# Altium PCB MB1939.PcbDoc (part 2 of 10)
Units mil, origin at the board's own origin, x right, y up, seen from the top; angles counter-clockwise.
Board outline 5910.64 x 4335.93 mil, 6 copper layers (Top Layer, l2_GND, L3_SIG, L4_VCC, L5_GND, Bottom Layer), stack 58.424 mil thick; 635 components, 489 nets, 2289 pads, 1388 vias.
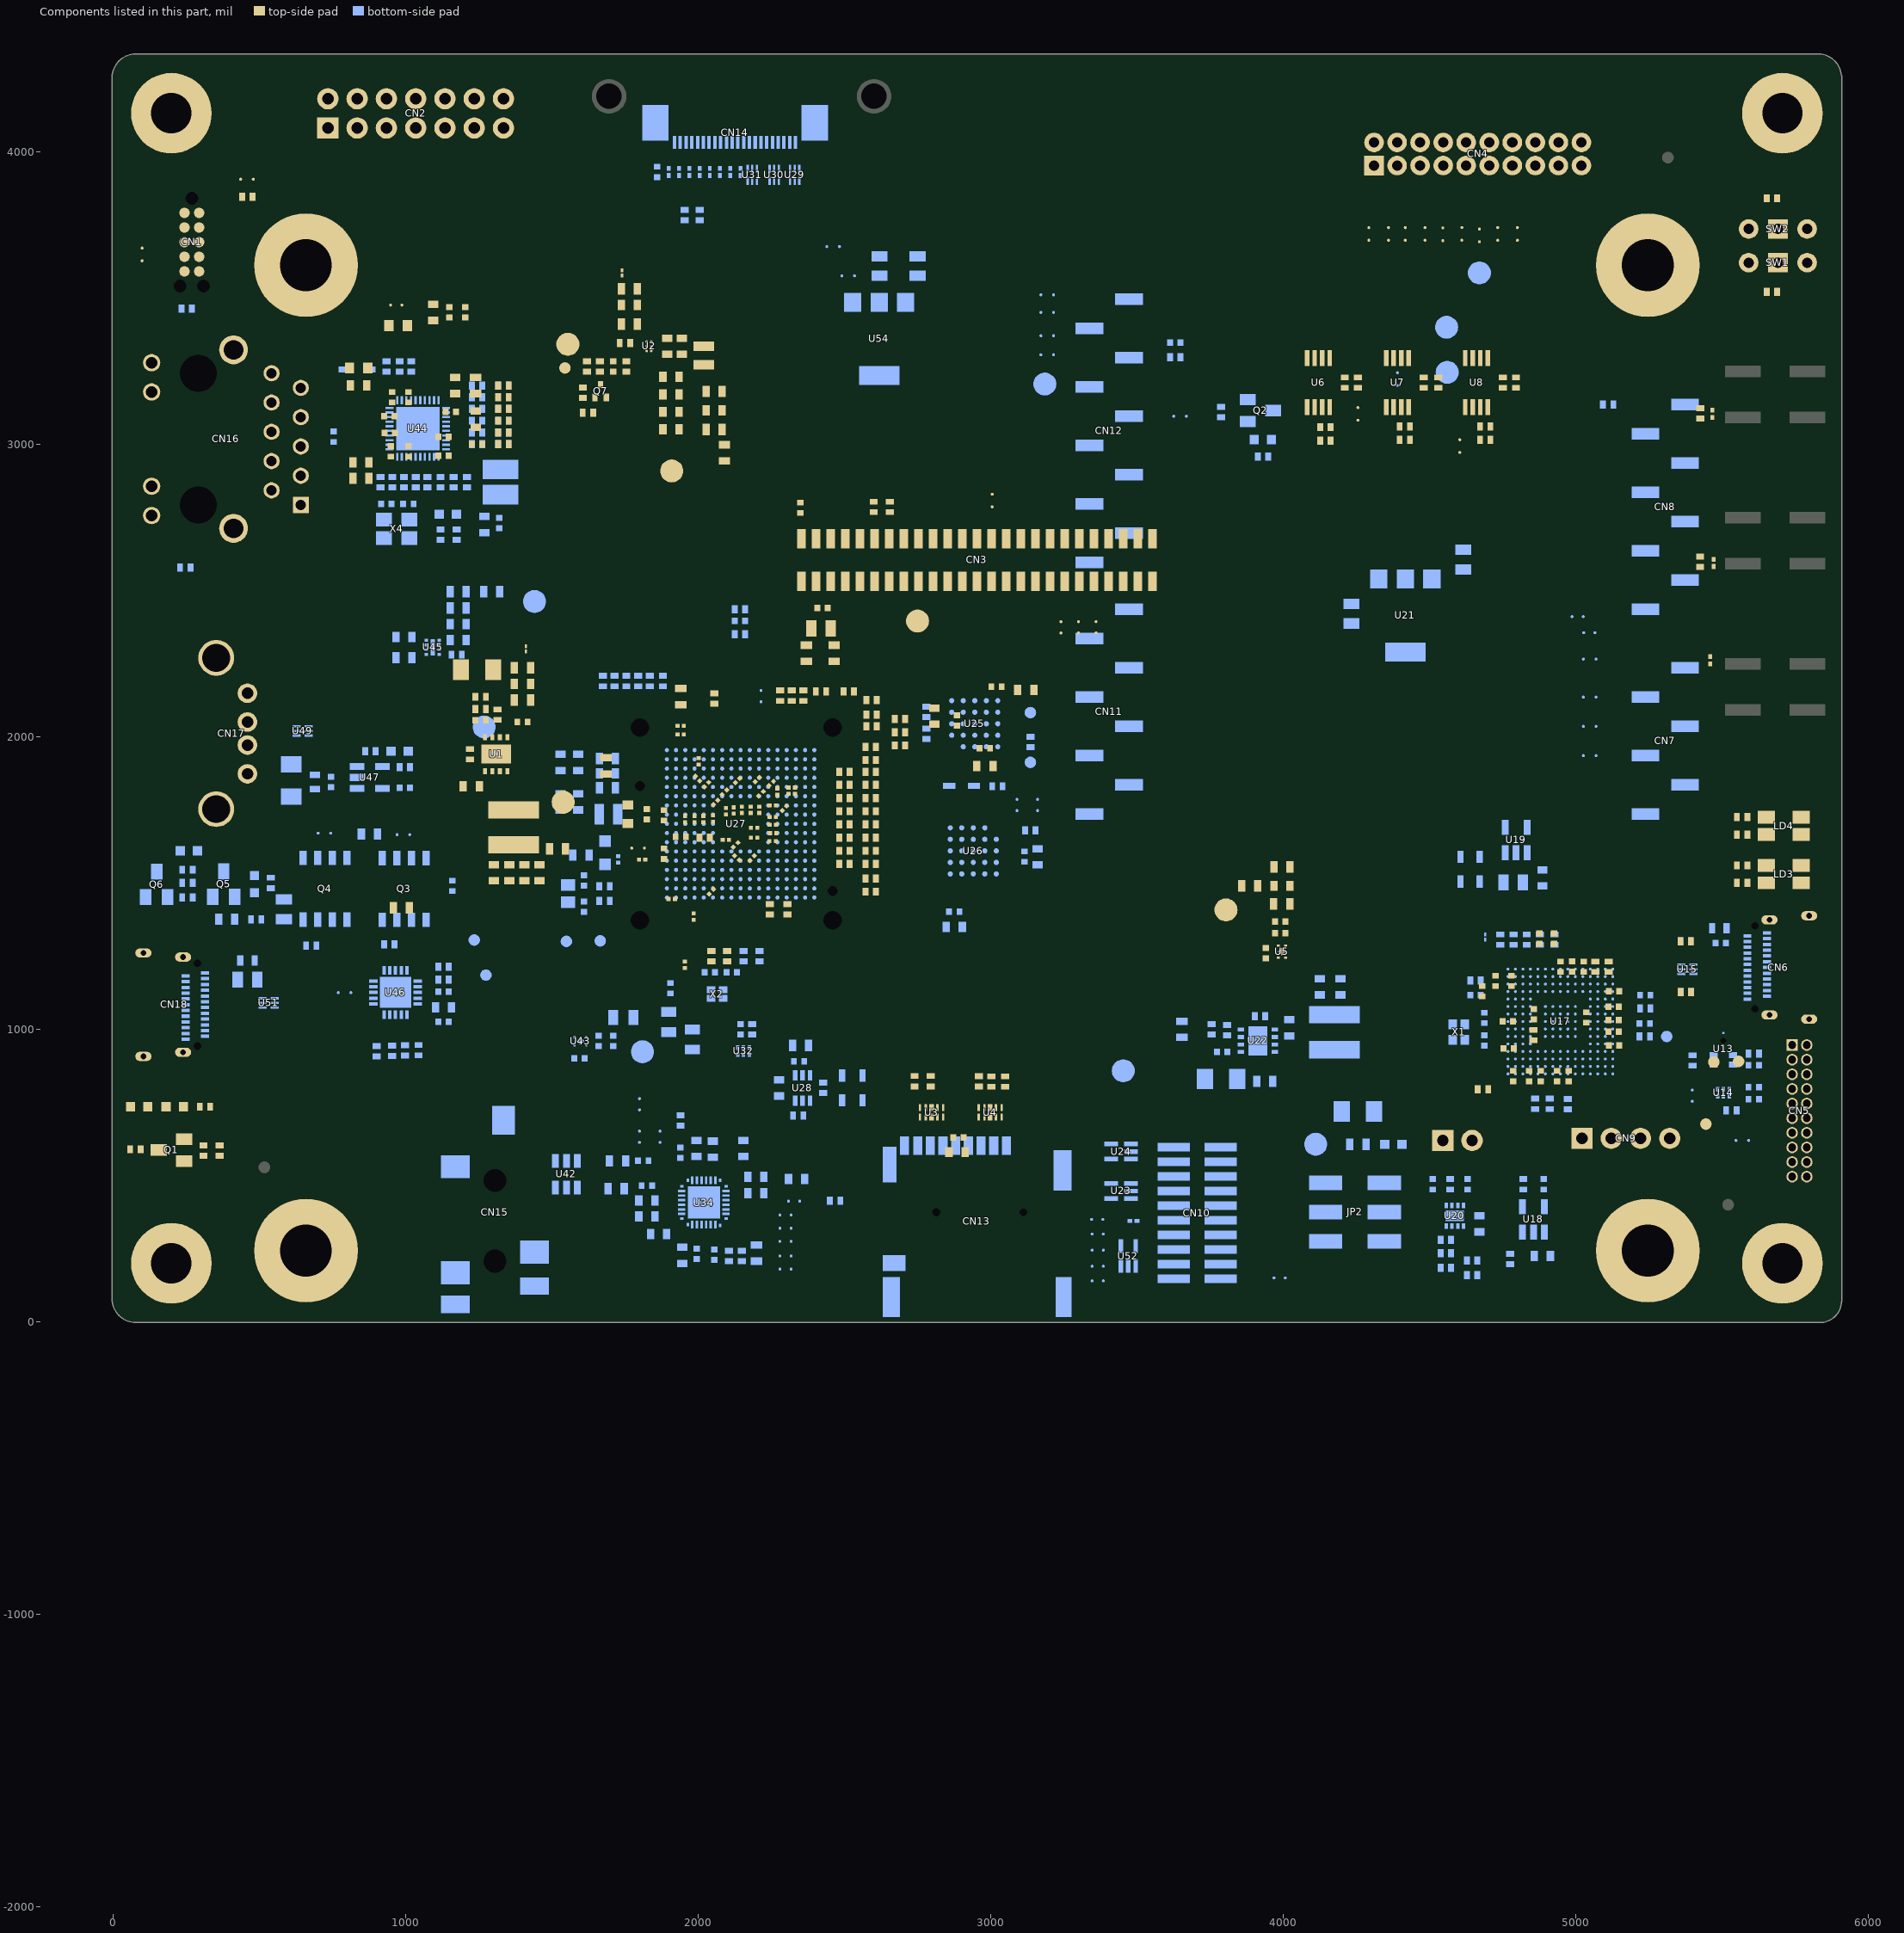
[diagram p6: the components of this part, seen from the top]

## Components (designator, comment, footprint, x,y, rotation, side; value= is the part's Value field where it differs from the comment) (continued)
R151 "Resistor" R0402 2142.73,2350 r180 bottom locked value=10K
R152 "Resistor" R0402 2142.73,2435 r0 bottom locked value=140K
R153 "Resistor" R0402 2155,1250 r90 bottom locked value=1K5
R154 "Resistor" R0402 2100,1250 r90 bottom locked value=0R
R155 "Resistor" R0402 2045,1250 r90 bottom locked value=0R
R156 "Resistor" R0402 1940,687.72 r270 bottom value=2K2
R157 "Resistor" R0402 1620,3265 r90 top value=422K
R158 "Resistor" R0402 1606.3,3175.2 r90 top value=150K
R159 "Resistor" R0805 1981.1,965 r90 bottom value=0R
R160 "Resistor" R0402 1880,2190 r90 bottom locked value=22R
R161 "Resistor" R0402 1835,2190 r90 bottom locked value=22R
R162 "Resistor" R0402 1795,2190 r90 bottom locked value=22R
R163 "Resistor" R0805 1745.01,1040 r0 bottom locked value=0R
R164 "Resistor" R0603 1725,550 r0 bottom value=20R
R165 "Resistor" R0603 1720,455 r0 bottom value=20R
R166 "Resistor" R0402 1755,2190 r90 bottom locked value=22R
R167 "Resistor" R0603 1690.01,1825 r180 bottom locked value=0R
R168 "Resistor" R0603 1690.01,1925 r180 bottom locked value=50mR
R169 "Resistor" R0402 1715,2190 r90 bottom locked value=22R
R170 "Resistor" R0402 1680.4,1438.69 r0 bottom locked value=0R
R171 "Resistor" R0402 1680.4,1488.69 r0 bottom locked value=0R
R172 "Resistor" R0402 1675,2190 r90 bottom locked value=22R
R173 "Resistor" R0603 1600.01,1595 r180 bottom locked value=0R
R174 "Resistor" R0402 1335.01,3080 r0 bottom locked value=4K7
R175 "Resistor" R0402 1335.01,3200 r0 bottom locked value=4K7
R176 "Resistor" R0402 1335,3000 r0 bottom locked value=4K7
R177 "Resistor" R0402 1335,3040 r0 bottom locked value=4K7
R178 "Resistor" R0402 1335,3120 r0 bottom locked value=4K7
R179 "Resistor" R0603 1295.01,2495 r0 bottom locked value=0R
R180 "Resistor" R0402 1245.01,3000 r180 bottom locked value=22R
R181 "Resistor" R0402 1245.01,3040 r180 bottom locked value=22R
R182 "Resistor" R0402 1245.01,3080 r180 bottom locked value=22R
R183 "Resistor" R0402 1245.01,3120 r180 bottom locked value=22R
R184 "Resistor" R0402 1245.01,3160 r180 bottom locked value=22R
R185 "Resistor" R0402 1245.01,3200 r180 bottom locked value=22R
R186 "Resistor" R0402 1210,2870 r270 bottom locked value=1K5
R187 "Resistor" R0603 1180.01,2440 r0 bottom locked value=0R
R188 "Resistor" R0603 1180.01,2495 r0 bottom locked value=330mR
R189 "Resistor" R0402 1175,2280 r180 bottom locked value=0R
R190 "Resistor" R0402 1175,2690 r90 bottom locked value=510R
R191 "Resistor" R0402 1165,2870 r90 bottom locked value=4K7
R192 "Resistor" R0402 1130.01,1169 r0 bottom value=24K
R193 "Resistor" R0402 1130.01,1214 r180 bottom value=100K
R194 "Resistor" R0402 1120,2690 r90 bottom locked value=4K7
R195 "Resistor" R0402 1120,2870 r90 bottom locked value=4K7
R196 "Resistor" R0402 1075,2870 r90 bottom locked value=22R
R197 "Resistor" R0402 1045.01,928.49 r270 bottom locked value=10K
R198 "Resistor" R0402 1035,2870 r90 bottom locked value=0R
R199 "Resistor" R0603 995.01,2270 r0 bottom locked value=0R
R200 "Resistor" R0402 1020,3265 r90 bottom locked value=1K5
R201 "Resistor" R0402 998,1895.51 r180 bottom locked value=100K
R202 "Resistor" R0402 999.01,927.49 r90 bottom locked value=0R
R203 "Resistor" R0402 995,2870 r270 bottom locked value=22R
R204 "Resistor" R0402 980,3265 r90 bottom locked value=1K5
R205 "Resistor" R0402 955,2870 r90 bottom locked value=0R
R206 "Resistor" R0402 954.01,926.49 r90 bottom locked value=0R
R207 "Resistor" R0402 935,3265 r270 bottom locked value=10K
R208 "Resistor" R0402 915,2870 r270 bottom locked value=2K49
R209 "Resistor" R0603 877,1667 r180 bottom value=0R
R210 "Resistor" R0402 902.01,924.49 r90 bottom locked value=100K
R211 "Resistor" R0402 880,1950 r0 bottom locked value=680R
R212 "Resistor" R0402 540,1500 r270 bottom locked value=270R
R213 "Resistor" R0402 490.01,1375 r180 bottom locked value=47K
R214 "Resistor" R0603 389.01,1375.94 r180 bottom locked value=22K
R215 "Resistor" R0402 255.01,1450 r180 bottom locked value=100K
R216 "Resistor" R0402 255.01,1500 r0 bottom locked value=47K
R217 "Resistor" R0402 255.01,1545 r0 bottom locked value=330R
R218 "Resistor" R0402 252.64,3462.83 r180 bottom locked value=510R
R219 "Resistor" R0402 247.64,2577.83 r0 bottom locked value=510R
R220 "Resistor" R0402 2022.28,1655 r0 top value=2R
R221 "Resistor" R0402 2005,3782.28 r90 bottom value=10K
R222 "Resistor" R0402 1954.02,3782.28 r90 bottom value=10K
R223 "Resistor" R0402 1623.6,3107.4 r180 top value=1M
R224 "Resistor" R0402 5425,3105 r270 top value=10K
R225 "Resistor" R0402 5424.29,2597.72 r270 top value=10K
R226 "Resistor" R0402 2150,225 r270 bottom value=0R
R227 "Resistor" R0402 2105,225 r270 bottom value=0R
R228 "Resistor" R0402 945,1290 r0 bottom value=1M3
R229 "Resistor" R0402 678,1286 r0 bottom value=1M3
SB1 "SB_ON" SOLDER-BRIDGE_R0603-0R 100,3650 r270 top locked value=0R
SB2 "SB_ON" SOLDER-BRIDGE_R0603-0R 456.4,3905 r0 top locked value=0R
SB3 "SB_ON" SOLDER-BRIDGE_R0402-0R 970.02,3475 r180 top locked value=0R
SB4 "SB_ON" SOLDER-BRIDGE_R0603-0R 1793,1619 r0 top value=0R
SB5 "SB_ON" SOLDER-BRIDGE_R0603-0R 3005,2805 r90 top locked value=0R
SB6 "SB_ON" SOLDER-BRIDGE_R0402-0R 3240,2375 r270 top locked value=0R
SB7 "SB_ON" SOLDER-BRIDGE_R0402-0R 3300,2375.32 r270 top locked value=0R
SB8 "SB_ON" SOLDER-BRIDGE_R0402-0R 3360,2375.32 r270 top locked value=0R
SB9 "SB_ON" SOLDER-BRIDGE_R0603-0R 4255,3105 r270 top locked value=0R
SB10 "SB_ON" SOLDER-BRIDGE_R0603-0R 4292.17,3716.06 r90 top locked value=0R
SB11 "SB_ON" SOLDER-BRIDGE_R0603-0R 4359.49,3716.06 r90 top locked value=0R
SB12 "SB_ON" SOLDER-BRIDGE_R0603-0R 4416.81,3716.06 r90 top locked value=0R
SB13 "SB_ON" SOLDER-BRIDGE_R0603-0R 4484.13,3716.06 r90 top locked value=0R
SB14 "SB_ON" SOLDER-BRIDGE_R0603-0R 4545,3715 r90 top locked value=0R
SB15 "SB_ON" SOLDER-BRIDGE_R0603-0R 4610,3716.38 r90 top locked value=0R
SB16 "SB_ON" SOLDER-BRIDGE_R0603-0R 4670,3715 r270 top locked value=0R
SB17 "SB_ON" SOLDER-BRIDGE_R0603-0R 4732.52,3716.06 r90 top locked value=0R
SB18 "SB_ON" SOLDER-BRIDGE_R0603-0R 4799.84,3716.06 r90 top locked value=0R
SB19 "SB_ON" SOLDER-BRIDGE_R0402-0R 5397.38,771.51 r90 bottom locked value=0R
SB20 "SB_ON" SOLDER-BRIDGE_R0603-0R 5045.02,1935 r0 bottom locked value=0R
SB21 "SB_ON" SOLDER-BRIDGE_R0603-0R 5045.02,2035 r0 bottom locked value=0R
SB22 "SB_ON" SOLDER-BRIDGE_R0603-0R 5045.02,2135 r0 bottom locked value=0R
SB23 "SB_ON" SOLDER-BRIDGE_R0603-0R 5045.02,2265 r0 bottom locked value=0R
SB25 "SB_ON" SOLDER-BRIDGE_R0603-0R 3645.02,3095 r0 bottom locked value=0R
SB26 "SB_ON" SOLDER-BRIDGE_R0402-0R 3367.28,245 r180 bottom value=0R
SB27 "SB_ON" SOLDER-BRIDGE_R0402-0R 3367.28,140 r180 bottom value=0R
SB28 "SB_ON" SOLDER-BRIDGE_R0402-0R 3367.28,190 r180 bottom value=0R
SB29 "SB_ON" SOLDER-BRIDGE_R0402-0R 3365.67,350 r180 bottom value=0R
SB30 "SB_ON" SOLDER-BRIDGE_R0402-0R 3367.28,300 r180 bottom value=0R
SB31 "SB_ON" SOLDER-BRIDGE_R0603-0R 3195,3305 r180 bottom locked value=0R
SB32 "SB_ON" SOLDER-BRIDGE_R0603-0R 3195,3370 r180 bottom locked value=0R
SB33 "SB_ON" SOLDER-BRIDGE_R0603-0R 3195,3450 r180 bottom locked value=0R
SB34 "SB_ON" SOLDER-BRIDGE_R0603-0R 3195,3510 r180 bottom locked value=0R
SB35 "SB_ON" SOLDER-BRIDGE_R0402-0R 3160,1765 r90 bottom locked value=0R
SB36 "SB_ON" SOLDER-BRIDGE_R0402-0R 3090,1765 r90 bottom locked value=0R
SB37 "SB_ON" SOLDER-BRIDGE_R0402-0R 2329.74,412.65 r180 bottom locked value=0R
SB38 "SB_ON" SOLDER-BRIDGE_R0402-0R 1800,745 r270 bottom value=0R
SB39 "SB_ON" SOLDER-BRIDGE_R0402-0R 1800,633.94 r270 bottom value=0R
SB40 "SB_ON" SOLDER-BRIDGE_R0402-0R 1870,633.94 r270 bottom value=0R
SB41 "SB_ON" SOLDER-BRIDGE_R0603-0R 5570.32,620 r180 bottom value=0R
SB42 "SB_ON" SOLDER-BRIDGE_R0402-0R 5007.28,2410 r180 bottom value=0R
SB43 "SB_ON" SOLDER-BRIDGE_R0402-0R 2215,2140 r270 bottom locked value=0R
SB44 "SB_ON" SOLDER-BRIDGE_R0402-0R 5044.33,2355 r0 bottom value=0R
SB45 "SB_ON" SOLDER-BRIDGE_R0603-0R 2459.59,3674.9 r0 bottom value=0R
SB46 "SB_ON" SOLDER-BRIDGE_R0603-0R 995,1665 r180 bottom locked value=0R
SB47 "SB_ON" SOLDER-BRIDGE_R0603-0R 790.02,1125 r0 bottom locked value=0R
SB48 "SB_ON" SOLDER-BRIDGE_R0603-0R 725,1670 r180 bottom value=0R
SB49 "SB_ON" SOLDER-BRIDGE_R0603-0R 4603,2995 r270 top value=0R
SB51 "SB_ON" SOLDER-BRIDGE_R0603-0R 4390,3220 r90 bottom value=0R
SB53 "SB_ON" SOLDER-BRIDGE_R0603-0R 2515,3575 r180 bottom value=0R
SB54 "SB_ON" SOLDER-BRIDGE_R0402-0R 3989,150 r180 bottom value=0R
SB55 "SB_ON" SOLDER-BRIDGE_R0402-0R 2297.28,365 r0 bottom value=0R
SB56 "SB_ON" SOLDER-BRIDGE_R0402-0R 2297.28,320 r0 bottom value=0R
SB57 "SB_ON" SOLDER-BRIDGE_R0402-0R 2297.28,275 r0 bottom value=0R
SB58 "SB_ON" SOLDER-BRIDGE_R0402-0R 2297.28,180 r0 bottom value=0R
SB59 "SB_ON" SOLDER-BRIDGE_R0402-0R 2297.28,225 r0 bottom value=0R
SW1 "SW_MECA_1K2" SWI_EAO_09-03290-01_EXTENDED_STRAIGHT_BLACK 5690,3620 r270 top locked value=09.03290.01
SW2 "SW_MECA_1K2" SWI_EAO_09-03290-01_EXTENDED_STRAIGHT_BLACK 5690,3735 r270 top locked value=09.03290.01
TP1 "Test Point" TP_SMD_2MM 2750,2395 r0 top locked value=N/A
TP2 "Test Point" TP_SMD_1MM 5310,975 r270 bottom locked value=N/A
TP3 "Test Point" TP_SMD_2MM 4670,3585 r0 bottom locked value=N/A
TP4 "Test Point" TP_SMD_2MM 4110.51,607.01 r270 bottom locked value=N/A
TP5 "Test Point" TP_SMD_2MM 3185,3205 r270 bottom locked value=N/A
TP6 "Test Point" TP_SMD_1MM 3135.51,1912.01 r180 bottom locked value=N/A
TP7 "Test Point" TP_SMD_1MM 3135.51,2082.01 r180 bottom locked value=N/A
TP8 "Test Point" TP_SMD_1MM 1665.51,1302.01 r0 bottom locked value=N/A
TP9 "Test Point" TP_SMD_1MM 1550,1300 r0 bottom locked value=N/A
TP10 "Test Point" TP_SMD_2MM 1910,2908 r90 top value=N/A
TP11 "Test Point" TP_SMD_2MM 1555,3341 r180 top value=N/A
TP12 "Test Point" TP_SMD_2MM 1269,2033 r90 bottom value=N/A
TP13 "Test Point" TP_SMD_2MM 3804,1408 r90 top value=N/A
TP14 "Test Point" TP_SMD_2MM 1539,1776 r90 top value=N/A
TP15 "Test Point" TP_SMD_2MM 1810,923 r270 bottom value=N/A
TP16 "Test Point" TP_SMD_2MM 3453,858 r90 bottom value=N/A
TP17 "Test Point" TP_SMD_2MM 1441,2462 r90 bottom value=N/A
TP18 "Test Point" TP_SMD_1MM 5444,676 r90 top value=N/A
TP19 "Test Point" TP_SMD_1MM 5555.85,890 r90 top value=N/A
TP20 "Test Point" TP_SMD_1MM 5471,888 r90 top value=N/A
TP21 "Test Point" TP_SMD_2MM 4560,3245 r90 bottom value=N/A
TP22 "Test Point" TP_SMD_2MM 4558,3399 r90 bottom value=N/A
TP23 "Test Point" TP_SMD_1MM 1275,1185 r90 bottom value=N/A
TP24 "Test Point" TP_SMD_1MM 1235,1305 r90 bottom value=N/A
TP25 "Test Point" TP_SMD_1MM 1545,3260 r90 top value=N/A
U1 "ST1S31PUR" ICC_VFDFPN8-EPAD_3X3_P065 1310.01,1940 r180 top locked
U2 "TPS62088YFP" ICC_DSBGA6_YFP_0P80X1P20_H0P50_P040 1832.13,3334.25 r0 top
U3 "HSP051-4M10" ESD_UQFN-10L_2P5X1_P050 2798,716 r0 top
U4 "HSP051-4M10" ESD_UQFN-10L_2P5X1_P050 2998,716 r0 top
U5 "LD39020" REG_XDFN4-EPAD_CASE-711AJ_1X1_H0P4_P065 3995.01,1264.99 r180 top locked value=LD39020ADTPU33R
U6 "TSZ122IST" ICC_MINISO8_3X3_P065 4120,3210 r180 top locked
U7 "TSZ122IST" ICC_MINISO8_3X3_P065 4390,3210 r180 top locked
U8 "TSZ122IST" ICC_MINISO8_3X3_P065 4660,3210 r180 top locked
U9 "ESD-TRANSIL" ESD_ST0201 5458.74,2261.04 r90 top value=ESDALC6V1-1U2
U10 "ESD-TRANSIL" ESD_ST0201 5470,2593.72 r90 top value=ESDALC6V1-1U2
U12 "ESD-TRANSIL" ESD_ST0201 5466.26,3103.56 r90 top value=ESDALC6V1-1U2
U13 "MP23DB01MMTR" MIC_STM_MP23DB01MMTR 5503.69,933 r0 bottom locked value=MP23DB01HPTR
U14 "NX3L1T3157GM" ICC_SOT886_XSON6 5503.84,783.16 r0 bottom locked value=NX3L1T3157GMZ
U15 "ECMF2-40A100N6" ESD_UQFN-6L_1P45X1P4_P040 5381,1205 r270 bottom
U16 "ESD-TRANSIL" ESD_QFN1610_2N_1K_2A 5490,1345 r180 bottom value=ESDA25P35-1U1M
U17 "STLINK-V3EC" ICC_UFBGA201_176+25_10X10_P065 4946.7,1026.42 r0 bottom locked value=STM32F723IEK6
U18 "STMPS2151STR" MOS_SOT23-5L 4855.01,350 r180 bottom locked
U19 "ST730M33R" ICC_SOT23-5L_H1P45 4795.52,1647.01 r180 bottom locked
U20 "TPS259535DSG" ICC_WSON8-EPAD_2X2_P050 4585.99,362.44 r270 bottom locked
U21 "LD1117S50TR" REG_SOT223-TAB 4417.02,2414.49 r0 bottom locked
U22 "ST1S31PUR" ICC_VFDFPN8-EPAD_3X3_P065 3913,960.5 r90 bottom locked
U23 "ESDALC6V1W5" ESD_SOT323-5L 3445.52,447.01 r270 bottom locked
U24 "ESDALC6V1W5" ESD_SOT323-5L 3445.52,582.01 r270 bottom locked
U25 "MX66UW1G45GXDI00" ICC_BGA24_5X5-BALL-ARRAY_6X8_P1 2945.51,2044.01 r0 bottom locked
U26 "APS256XXN-OBR-BG" ICC_BGA24_5X5-BALL-ARRAY_6X8_P1 2940.51,1609.64 r180 bottom locked
U27 "STM32N657X0H3Q" ICC_VFBGA264_14X14_P080_SOCKET_IRONWOOD_SG-BGA-6112MF 2130.59,1702.01 r0 bottom
U28 "TPS22919" ICC_SC70-6_DCK_R-PDSO-G6_2X1P25_P065 2357.01,799.49 r0 bottom locked value=TPS22919DCKR
U29 "ECMF2-40A100N6" ESD_UQFN-6L_1P45X1P4_P040 2330,3920 r0 bottom
U30 "ECMF2-40A100N6" ESD_UQFN-6L_1P45X1P4_P040 2260,3920 r0 bottom
U31 "ECMF2-40A100N6" ESD_UQFN-6L_1P45X1P4_P040 2185,3920 r0 bottom
U32 "NX3L1T3157GM" ICC_SOT886_XSON6 2154.99,925 r180 bottom locked value=NX3L1T3157GMZ
U33 "ESD-TRANSIL" ESD_ST0201 2145,3930 r270 bottom value=ESDALC6V1-1U2
U34 "WM8904CGEFL/RV" ICC_QFN32-EPAD_4X4_P040 2019.65,407.97 r180 bottom
U35 "ESD-TRANSIL" ESD_ST0201 2110,3930 r270 bottom value=ESDALC6V1-1U2
U36 "ESD-TRANSIL" ESD_ST0201 2075,3930 r270 bottom value=ESDALC6V1-1U2
U37 "ESD-TRANSIL" ESD_ST0201 2040,3930 r270 bottom value=ESDALC6V1-1U2
U38 "ESD-TRANSIL" ESD_ST0201 2005,3930 r270 bottom value=ESDALC6V1-1U2
U39 "ESD-TRANSIL" ESD_ST0201 1970,3930 r270 bottom value=ESDALC6V1-1U2
U40 "ESD-TRANSIL" ESD_ST0201 1935,3930 r270 bottom value=ESDALC6V1-1U2
U41 "ESD-TRANSIL" ESD_ST0201 1900,3930 r270 bottom value=ESDALC6V1-1U2
U42 "ESDA6V1BC6" ESD_SOT23-6L 1550,504.5 r180 bottom
U43 "LD39020" REG_XDFN4-EPAD_CASE-711AJ_1X1_H0P4_P065 1598,959.49 r270 bottom locked value=LD39020ADTPU18R
U44 "RTL8211F-CG" ICC_QFN40-EPAD_5X5_P040 1042.64,3052.83 r0 bottom locked
U45 "LD56100DPU18R" ICC_DFN8-EPAD_1P6X1P2_P040_H0P45 1093.55,2305.19 r270 bottom locked
U46 "TCPP03-M20" ICC_QFN20-EPAD_4X4_P050 966.02,1125.7 r0 bottom locked
U47 "STMPS2151STR" MOS_SOT23-5L 878,1860.51 r90 bottom locked
U48 "​Footprint needed DFN105P160X60-2N" ESD_QFN1610_2N_1K_2A 690,1845 r90 bottom locked value=ESDA7P120-1U1M
U49 "ECMF2-40A100N6" ESD_UQFN-6L_1P45X1P4_P040 648.65,2019.35 r90 bottom
U50 "ESD-TRANSIL" ESD_QFN1610_2N_1K_2A 460,1235 r0 bottom value=ESDA25P35-1U1M
U51 "ECMF2-40A100N6" ESD_UQFN-6L_1P45X1P4_P040 533,1090 r90 bottom
U52 "ESDALC6V1W5" ESD_SOT323-5L 3470,225 r180 bottom
U53 "ESD-TRANSIL" ESD_ST0201 3487.7,345 r180 bottom value=ESDALC6V1-1U2
U54 "LD1117S33TR" REG_SOT223-TAB 2618.91,3359.3 r0 bottom locked
X1 "XTAL_4_PINS" CRY_NX2016SA_4P 4600.01,989.99 r90 bottom locked value=24MHz
X2 "XTAL_4_PINS" CRY_NX1612SA_4P 2065.01,1120 r0 bottom locked value=48MHz
X3 "XTAL_2_PINS" CRY_NX2012SA_2P 1555.39,1463.69 r90 bottom locked value=32.768KHz
X4 "XTAL_4_PINS" CRY_NX3225HA_4P 970.01,2710 r180 bottom locked value=25MHz

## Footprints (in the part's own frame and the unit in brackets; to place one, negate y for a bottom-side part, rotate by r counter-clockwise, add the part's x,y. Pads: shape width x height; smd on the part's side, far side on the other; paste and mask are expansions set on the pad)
C0201_MURATA_GRM033_H0P3 [mm] "GRM033R60J105ME11"
  rect 0.35x0.35 smd mask+0.05: 1(-0.275,0) 2(0.275,0)
  body extent -0.32,-0.17 0.32,0.17, height 0.33
C0402 [mm]
  rect 0.51x0.56 smd mask+0.05: 1(-0.45,0) 2(0.45,0)
  body extent -0.5,-0.3 0.5,0.3, height 0.4
C0603 [mm]
  rect 0.64x0.89 smd mask+0.05: 1(-0.7,0) 2(0.7,0)
  silkscreen extent -1.05,-0.55 1.02,0.55, body extent -0.9,-0.5 0.9,0.5, height 1.4
C0805 [mm]
  rect 0.9x1.4 smd mask+0.05: 1(-0.85,0) 2(0.85,0)
  silkscreen extent -1.3,-0.77 1.3,0.77, body extent -1.1,-0.7 1.1,0.7, height 1.35
C0805_H0P6 [mm] "MCD-01549"
  rect 0.9x1.4 smd mask+0.05: 1(-0.85,0) 2(0.85,0)
  silkscreen extent -1.1,-0.77 1.1,0.77, body extent -1.1,-0.7 1.1,0.7, height 0.7
C1206_H1P6 [mm]
  rect 1.4x1.78 smd mask+0.05: 1(-1.4,0) 2(1.4,0)
  silkscreen extent -2.12,-0.97 2.15,0.97, body extent -1.7,-0.9 1.7,0.9, height 1.8
CON_FCI_20021311-XXX20XXLF [mm]
  rect 1x1 / inner round 1 / far side rect 1x1 hole 0.7 mask+0.05: 1(5.715,0.635)
  round 1 hole 0.7 mask+0.05: 2(5.715,-0.635) 3(4.445,0.635) 4(4.445,-0.635) 5(3.175,0.635) 6(3.175,-0.635) 7(1.905,0.635) 8(1.905,-0.635) 9(0.635,0.635) 10(0.635,-0.635) 11(-0.635,0.635) 12(-0.635,-0.635) 13(-1.905,0.635) 14(-1.905,-0.635) 15(-3.175,0.635) 16(-3.175,-0.635) 17(-4.445,0.635) 18(-4.445,-0.635) 19(-5.715,0.635) 20(-5.715,-0.635)
  silkscreen extent -6.58,-1.5 6.58,1.5, body extent -6.58,-1.5 6.58,1.5, height 4.4
CON_MICROSD_YAMAICHI_PJS008-2003-1 [mm] "WITH POSITIONNING PINS"
  rect 1.6x0.8 smd paste+0 mask+0.05: 1(-15.6,-2.525) 2(-15.6,-1.425) 3(-15.6,-0.325) 4(-15.6,0.775) 5(-15.6,1.875) 6(-15.6,2.975) 7(-15.6,4.075) 8(-15.6,5.175) 9(-15.6,6.325)
  rect 1.4x1.95 smd paste+0 mask+0.05: 10(-5.4,7.225)
  rect 3.5x1.5 smd paste+0 mask+0.05: 11(-2.45,7.45)
  rect 3.5x1.4 smd paste+0 mask+0.05: 12(-2.45,-7.5)
  rect 3.5x1.6 smd paste+0 mask+0.05: 13(-13.45,-7.4)
  rect 3.1x1.2 smd paste+0 mask+0.05: 14(-13.95,7.6)
  round 0 hole 0.65 unplated mask+0.05: NPTH1(-9.8,-4)
  round 0 hole 0.7 unplated mask+0.05: NPTH2(-9.8,3.55)
  silkscreen extent -15.32,-7.25 5.65,7.25, body extent -15.25,-7.25 -0.45,7.42, height 2
CON_PHONE-JACK-3P5_HY_PJ3028B [mm]
  rect 1.5x2.5 smd mask+0.05: 2(1.25,-3.45) 7(2.85,3.45)
  rect 2x2.5 smd mask+0.05: 3(4,-3.45) 4(5.8,3.45) 6(13.2,-3.45)
  rect 2.5x2 smd mask+0.05: 5(17.25,0.75)
  round 0.5 hole 2 unplated mask+0.1: MT1(5,0) MT2(12,0)
  Multi-Layer keep-out circle w0.01: c12,0 r1.25
  Multi-Layer keep-out circle w0.01: c5,0 r1.25
  silkscreen extent -0.9,-3.7 16,3, body extent -0.9,-3 16,3, height 5
CON_RJ45_YD_48F-01GYDXNL_LED-P [mm]
  rect 1.4x1.4 hole 0.9 mask+0.05: 1(-5.715,16.29)
  round 1.4 hole 0.9 mask+0.05: 2(-4.445,13.75) 3(-3.175,16.29) 4(-1.905,13.75) 5(-0.635,16.29) 6(0.635,13.75) 7(1.905,16.29) 8(3.175,13.75) 9(4.445,16.29) 10(5.715,13.75)
  round 1.5 hole 1 mask+0.05: 11(-6.63,3.34) 12(-4.09,3.34) 13(4.09,3.34) 14(6.63,3.34)
  round 2.5 hole 1.7 mask+0.05: 15(7.75,10.45) 16(-7.75,10.45)
  round 1 hole 3.2 unplated mask+0.1: 17(-5.715,7.4) 18(5.715,7.4)
  Multi-Layer keep-out circle w0.01: c-5.715,7.4 r1.9
  Multi-Layer keep-out circle w0.01: c5.715,7.4 r1.9
  silkscreen extent -11.26,-3.5 11.26,18.34, body extent -11.4,-3.5 11.39,18.34, height 17
CON_SAMTEC_FLE-125-01-G-DV [mm]
  rect 0.74x1.675 smd mask+0.05: 1(-15.24,1.843) 2(-15.24,-1.843) 3(-13.97,1.843) 4(-13.97,-1.843) 5(-12.7,1.843) 6(-12.7,-1.843) 7(-11.43,1.843) 8(-11.43,-1.843) 9(-10.16,1.843) 10(-10.16,-1.843) 11(-8.89,1.843) 12(-8.89,-1.843) 13(-7.62,1.843) 14(-7.62,-1.843) 15(-6.35,1.843) 16(-6.35,-1.843) 17(-5.08,1.843) 18(-5.08,-1.843) 19(-3.81,1.843) 20(-3.81,-1.843) 21(-2.54,1.843) 22(-2.54,-1.843) 23(-1.27,1.843) 24(-1.27,-1.843) 25(0,1.843) 26(0,-1.843) 27(1.27,1.843) 28(1.27,-1.843) 29(2.54,1.843) 30(2.54,-1.843) 31(3.81,1.843) 32(3.81,-1.843) 33(5.08,1.843) 34(5.08,-1.843) 35(6.35,1.843) 36(6.35,-1.843) 37(7.62,1.843) 38(7.62,-1.843) 39(8.89,1.843) 40(8.89,-1.843) 41(10.16,1.843) 42(10.16,-1.843) 43(11.43,1.843) 44(11.43,-1.843) 45(12.7,1.843) 46(12.7,-1.843) 47(13.97,1.843) 48(13.97,-1.843) 49(15.24,1.843) 50(15.24,-1.843)
  silkscreen extent -16.38,-1.67 15.93,2.67, body extent -15.93,-2.3 15.93,2.3, height 4.55
CON_SAMTEC_FTSH-110-01-L-DV [mm]
  rect 0.74x2.79 smd mask+0.05: 1(-5.715,-2.035) 2(-5.715,2.035) 3(-4.445,-2.035) 4(-4.445,2.035) 5(-3.175,-2.035) 6(-3.175,2.035) 7(-1.905,-2.035) 8(-1.905,2.035) 9(-0.635,-2.035) 10(-0.635,2.035) 11(0.635,-2.035) 12(0.635,2.035) 13(1.905,-2.035) 14(1.905,2.035) 15(3.175,-2.035) 16(3.175,2.035) 17(4.445,-2.035) 18(4.445,2.035) 19(5.715,-2.035) 20(5.715,2.035)
  silkscreen extent -6.35,-1.71 6.35,1.71, body extent -6.35,-2.92 6.35,2.92, height 5.97
CON_SAMTEC_SQT-110-01-F-D-RA__STMOD+ [mm] "SQT-110-01-F-D-RA (connecteur SAMTEC pour interface STMod+ femelle cot?Host) Pinning adapt?non conforme SAMTEC."
  rect 1.7x1.7 hole 0.9 mask+0.05: 1(9,1)
  round 1.7 hole 0.9 mask+0.05: 2(7,1) 3(5,1) 4(3,1) 5(1,1) 6(-1,1) 7(-3,1) 8(-5,1) 9(-7,1) 10(-9,1) 11(9,-1) 12(7,-1) 13(5,-1) 14(3,-1) 15(1,-1) 16(-1,-1) 17(-3,-1) 18(-5,-1) 19(-7,-1) 20(-9,-1)
  silkscreen extent -10.15,-8.62 10.15,0.07, body extent -10.15,-8.65 10.15,1.22, height 4
CON_SAMTEC_SSW-106-22-X-S-VS [mil]
  rect 40x95 smd mask+1.97: 1(250,67.5) 2(150,-67.5) 3(50,67.5) 4(-50,-67.5) 5(-150,67.5) 6(-250,-67.5)
  silkscreen extent -310,-48 310,48, body extent -310,-101 310,102, height 385
CON_SAMTEC_SSW-108-22-X-S-VS [mil]
  rect 40x95 smd mask+1.97: 1(350,67.5) 2(250,-67.5) 3(150,67.5) 4(50,-67.5) 5(-50,67.5) 6(-150,-67.5) 7(-250,67.48) 8(-350,-67.48)
  silkscreen extent -410,-48 410,48, body extent -410,-101 410,102, height 385
CON_SAMTEC_SSW-110-22-X-S-VS [mil]
  rect 40x95 smd mask+1.97: 1(450,67.5) 2(350,-67.5) 3(250,67.5) 4(150,-67.5) 5(50,67.5) 6(-50,-67.5) 7(-150,67.48) 8(-250,-67.48) 9(-350,67.48) 10(-450,-67.48)
  silkscreen extent -510,-48 510,48, body extent -510,-101 510,102, height 385
CON_SAMTEC_TSM-103-01-X-DV [mm] "MCD-03177"
  rect 1.3x2.9 smd paste+0 mask+0.05: 1(-2.54,-2.55) 2(-2.54,2.55) 3(0,-2.55) 4(0,2.55) 5(2.54,-2.55) 6(2.54,2.55)
  silkscreen extent -3.97,-2.22 3.97,2.22, body extent -3.81,-3.85 3.81,3.85, height 9.65
CON_SAMTEC_TSW-102-07-G-S [mm]
  rect 1.85x1.85 / inner round 1.85 / far side rect 1.85x1.85 hole 1 mask+0.05: 1(-1.27,0)
  round 1.85 hole 1 mask+0.05: 2(1.27,0)
  silkscreen extent -2.58,-1.3 2.58,1.3, body extent -2.67,-1.3 2.58,1.3, height 8.38
CON_SAMTEC_TSW-104-07-G-S [mm]
  rect 1.85x1.85 / inner round 1.85 / far side rect 1.85x1.85 hole 1 mask+0.05: 1(-3.81,0)
  round 1.85 hole 1 mask+0.05: 2(-1.27,0) 3(1.27,0) 4(3.81,0)
  silkscreen extent -5.12,-1.3 5.12,1.3, body extent -5.21,-1.37 5.18,1.37, height 8.38
CON_SAMTEC_TSW-107-07-X-D [mm] "MCD-02123"
  rect 1.85x1.85 / inner round 1.85 / far side rect 1.85x1.85 hole 1 mask+0.05: 1(-7.62,-1.27)
  round 1.85 hole 1 mask+0.05: 2(-7.62,1.27) 3(-5.08,-1.27) 4(-5.08,1.27) 5(-2.54,-1.27) 6(-2.54,1.27) 7(0,-1.27) 8(0,1.27) 9(2.54,-1.27) 10(2.54,1.27) 11(5.08,-1.27) 12(5.08,1.27) 13(7.62,-1.27) 14(7.62,1.27)
  silkscreen extent -8.89,-2.54 8.89,2.54, body extent -8.89,-2.55 8.89,2.54, height 8.38
CON_TAG-C_TC2050-IDC-NL [mm]
  round 0.9 smd paste+0 mask+0.05: 1(-2.54,-0.635) 2(-1.27,-0.635) 3(0,-0.635) 4(1.27,-0.635) 5(2.54,-0.635) 6(2.54,0.635) 7(1.27,0.635) 8(0,0.635) 9(-1.27,0.635) 10(-2.54,0.635)
  round 0 hole 1.1 unplated mask+0.05: 11(-3.81,0) 12(3.81,-1.015) 13(3.81,1.015)
  Multi-Layer keep-out circle w0.01: c3.81,-1.015 r0.75
  Multi-Layer keep-out circle w0.01: c3.81,1.015 r0.75
  Multi-Layer keep-out circle w0.01: c-3.81,0 r0.75
  silkscreen extent -6.22,-3.4 6.22,3.33, body extent -6.28,-3.46 6.28,3.39, height 13
CON_TE-CONNECTIVITY_2-1734592-2_INV [mm] "MCD-03600"
  rect 0.3x1.1 smd mask+0.05: 1(5.25,1.7) 2(4.75,1.7) 3(4.25,1.7) 4(3.75,1.7) 5(3.25,1.7) 6(2.75,1.7) 7(2.25,1.7) 8(1.75,1.7) 9(1.25,1.7) 10(0.75,1.7) 11(0.25,1.7) 12(-0.25,1.7) 13(-0.75,1.7) 14(-1.25,1.7) 15(-1.75,1.7) 16(-2.25,1.7) 17(-2.75,1.7) 18(-3.25,1.7) 19(-3.75,1.7) 20(-4.25,1.7) 21(-4.75,1.7) 22(-5.25,1.7)
  rect 2.3x3.1 smd mask+0.05: S1(6.92,0) S2(-6.92,0)
  silkscreen extent -8.22,-3.06 8.21,1.35, body extent -8.22,-3.06 8.21,2.05, height 2.05
CON_USB-TYPEA_MOLEX_67643-3911_H7P73 [mm] "MCD-01475"
  round 1.7 hole 1 mask+0.1: 1(-3.5,12.99) 2(-1,12.99) 3(1,12.99) 4(3.5,12.99)
  round 3.1 hole 2.4 mask+0.1: 5(-6.57,10.28) 6(6.57,10.28)
  silkscreen extent -7.2,0 7.2,15.26, body extent -8,-0.01 8,15.26, height 8.03
CON_USB-TYPEC_AMPHENOL_12401826E412A [mm] "MCD-03232"
  round 0 hole 0.65 unplated mask+0.05: 0(-3.6,0)
  round 0 hole 0.65 slot 0.95 at 0 deg unplated mask+0.05: 0(3.6,0)
  rect 0.3x0.7 smd mask+0.05: A1(-2.75,0.66) A2(-2.25,0.66) A3(-1.75,0.66) A4(-1.25,0.66) A5(-0.75,0.66) A6(-0.25,0.66) A7(0.25,0.66) A8(0.75,0.66) A9(1.25,0.66) A10(1.75,0.66) A11(2.25,0.66) A12(2.75,0.66) B1(2.5,-1.04) B2(2,-1.04) B3(1.5,-1.04) B4(1,-1.04) B5(0.5,-1.04) B6(0,-1.04) B7(-0.5,-1.04) B8(-1,-1.04) B9(-1.5,-1.04) B10(-2,-1.04) B11(-2.5,-1.04) B12(-3,-1.04)
  oval 0.8x1.4 hole 0.5 slot 1.1 at 90 deg mask+0.05: SH1(-4.13,-1.25) SH2(4.13,-1.25) SH3(-4.49,-4.7) SH4(4.49,-4.7)
  Top Layer keep-out region: -3.75,-1.95 3.75,-1.95 3.75,-7.24 -3.75,-7.24
  silkscreen extent -4.6,-9.59 4.6,0.91, body extent -4.6,-9.59 4.6,0.91, height 3.26
CRY_NX1612SA_4P [mm] "MCD-02262"
  rect 0.75x0.6 smd mask+0.038: 1(-0.525,-0.375) 2(0.525,-0.375) 3(0.525,0.375) 4(-0.525,0.375)
  silkscreen extent -1.02,-0.8 0.03,0.6, body extent -0.8,-0.6 0.8,0.6, height 0.51
CRY_NX2012SA_2P [mm]
  rect 1x1.25 smd mask+0.05: 1(-0.75,0) 2(0.75,0)
  silkscreen extent -1.05,-0.75 1.05,0.75, body extent -1.05,-0.63 1.05,0.63, height 0.6
CRY_NX2016SA_4P [mm]
  rect 0.85x0.75 smd mask+0.05: 1(-0.675,-0.525) 2(0.675,-0.525) 3(0.675,0.525) 4(-0.675,0.525)
  silkscreen extent -1.22,-1.02 1.05,0.85, body extent -1.05,-0.85 1.05,0.85, height 0.7
CRY_NX3225HA_4P [mm]
  rect 1.4x1.2 smd mask+0.05: 1(-1.1,-0.8) 2(1.1,-0.8) 3(1.1,0.8) 4(-1.1,0.8)
  silkscreen extent -1.9,-1.5 1.65,1.3, body extent -1.66,-1.31 1.66,1.31, height 0.91
DIO_SOD323 [mm]
  rect 1.06x0.54 smd mask+0.05: 1(-1.07,0) 2(1.07,0)
  silkscreen extent -0.9,-0.72 0.9,0.72, body extent -1.3,-0.78 1.3,0.78, height 1.17
DIO_SOD323_1A_2K [mm]
  rect 1.06x0.54 smd mask+0.05: 1(-1.07,0) 2(1.07,0)
  silkscreen extent -0.9,-0.72 0.9,0.72, body extent -1.3,-0.78 1.3,0.78, height 1.17
ESD_QFN1610_2N_1K_2A [mm] "DFN, 2-Leads, Body 1.60x1.00mm"
  rect 0.55x0.9 smd mask+0.05: 1(-0.625,0) 2(0.625,0)
  silkscreen extent -1.02,-0.58 0.85,0.58, body extent -0.85,-0.55 0.85,0.55, height 0.6
ESD_SOT23-6L [mm]
  rect 0.6x1.2 smd mask+0.05: 1(-0.95,-1.15) 2(0,-1.15) 3(0.95,-1.15) 4(0.95,1.15) 5(0,1.15) 6(-0.95,1.15)
  silkscreen extent -1.53,-0.87 1.53,0.87, body extent -1.52,-1.5 1.52,1.5, height 1.45
ESD_SOT323-5L [mm]
  rect 0.4x1.2 smd mask+0.05: 1(-0.65,-0.85) 2(0,-0.85) 3(0.65,-0.85) 4(0.65,0.85) 5(-0.65,0.85)
  silkscreen extent -1.22,-1.21 1.22,0.77, body extent -1.15,-1.05 1.15,1.05, height 1.1
ESD_ST0201 [mm]
  rect 0.425x0.33 smd mask+0.05: 1(-0.312,0) 2(0.312,0)
  silkscreen extent -0.55,-0.3 0.33,0.3, body extent -0.34,-0.18 0.34,0.18, height 0.34
ESD_UQFN-6L_1P45X1P4_P040 [mm] "MCD-03060"
  rect 0.2x0.7 smd mask+0.05: 1(-0.4,-0.525) 2(0,-0.525) 3(0.4,-0.525) 4(0.4,0.525) 5(0,0.525) 6(-0.4,0.525)
  body extent -0.72,-0.7 0.72,0.7, height 0.51
ESD_UQFN-10L_2P5X1_P050 [mm]
  rect 0.2x0.58 smd mask+0.05: 1(-1,-0.41) 2(-0.5,-0.41) 4(0.5,-0.41) 5(1,-0.41) 6(1,0.41) 7(0.5,0.41) 9(-0.5,0.41) 10(-1,0.41)
  rect 0.4x0.58 smd mask+0.05: 3(0,-0.41) 8(0,0.41)
  silkscreen extent -1.38,-0.63 1.38,0.63, body extent -1.3,-0.55 1.3,0.55, height 0.51
FIL_0603_H0P65 [mm]
  rect 0.8x0.95 smd mask+0.05: 1(-0.8,0) 2(0.8,0)
  silkscreen extent -1.33,-0.6 1.33,0.6, body extent -0.87,-0.47 0.87,0.47, height 0.65
ICC_BGA24_5X5-BALL-ARRAY_6X8_P1 [mm]
  round 0.45 smd mask+0.05: A2(-1,2) A3(0,2) A4(1,2) A5(2,2) B1(-2,1) B2(-1,1) B3(0,1) B4(1,1) B5(2,1) C1(-2,0) C2(-1,0) C3(0,0) C4(1,0) C5(2,0) D1(-2,-1) D2(-1,-1) D3(0,-1) D4(1,-1) D5(2,-1) E1(-2,-2) E2(-1,-2) E3(0,-2) E4(1,-2) E5(2,-2)
  silkscreen extent -3.05,-4.05 3.05,4.05, body extent -3.05,-4.05 3.05,4.05, height 1.2
ICC_DFN8-EPAD_1P6X1P2_P040_H0P45 [mm] "MCD-02937"
  rect 0.26x0.3 smd mask+0.035: 1(-0.6,-0.55) 2(-0.2,-0.55) 3(0.2,-0.55) 4(0.6,-0.55) 5(0.6,0.55) 6(0.2,0.55) 7(-0.2,0.55) 8(-0.6,0.55)
  rect 1.4x0.4 smd mask+0.05: EP(0,0)
  silkscreen extent -0.97,-0.77 0.85,0.6, body extent -0.8,-0.65 0.8,0.65, height 0.51
ICC_DSBGA6_YFP_0P80X1P20_H0P50_P040 [mm] "MCD-02469"
  round 0.23 smd paste+0 mask+0.05: A1(-0.2,0.4) A2(0.2,0.4) B1(-0.2,0) B2(0.2,0) C1(-0.2,-0.4) C2(0.2,-0.4)
  silkscreen extent -0.55,-0.7 0.5,0.75, body extent -0.41,-0.61 0.41,0.61, height 0.51
ICC_MINISO8_3X3_P065 [mm]
  rect 0.4x1.4 smd mask+0.05: 1(0.975,2.125) 2(0.325,2.125) 3(-0.325,2.125) 4(-0.975,2.125) 5(-0.975,-2.125) 6(-0.325,-2.125) 7(0.325,-2.125) 8(0.975,-2.125)
  silkscreen extent -1.6,-1.55 1.6,1.55, body extent -1.6,-2.58 1.6,2.58, height 1.11
ICC_QFN20-EPAD_4X4_P050 [mm] "MCD-02130"
  rect 0.75x0.3 smd mask+0.05: 1(-1.925,1) 2(-1.925,0.5) 3(-1.925,0) 4(-1.925,-0.5) 5(-1.925,-1) 11(1.925,-1) 12(1.925,-0.5) 13(1.925,0) 14(1.925,0.5) 15(1.925,1)
  rect 0.3x0.75 smd mask+0.05: 6(-1,-1.925) 7(-0.5,-1.925) 8(0,-1.925) 9(0.5,-1.925) 10(1,-1.925) 16(1,1.925) 17(0.5,1.925) 18(0,1.925) 19(-0.5,1.925) 20(-1,1.925)
  rect 2.7x2.7 smd mask+0.05: 21(0,0)
  silkscreen extent -2.07,-2.07 2.07,2.07, body extent -2.13,-2.13 2.13,2.13, height 1.01
ICC_QFN32-EPAD_4X4_P040 [mm] "MCD-03196"
  rect 0.22x0.3 smd mask+0.05: 1(-1.4,-2) 8(1.4,-1.925) 17(1.4,1.925) 24(-1.4,1.925)
  rect 0.22x0.66 smd mask+0.05: 2(-1,-1.925) 3(-0.6,-1.925) 4(-0.2,-1.925) 5(0.2,-1.925) 6(0.6,-1.925) 7(1,-1.925) 18(1,1.925) 19(0.6,1.925) 20(0.2,1.925) 21(-0.2,1.925) 22(-0.6,1.925) 23(-1,1.925)
  rect 0.3x0.22 smd mask+0.05: 9(1.925,-1.4) 16(1.925,1.4) 25(-1.925,1.4) 32(-1.925,-1.4)
  rect 0.66x0.22 smd mask+0.05: 10(1.925,-1) 11(1.925,-0.6) 12(1.925,-0.2) 13(1.925,0.2) 14(1.925,0.6) 15(1.925,1) 26(-1.925,1) 27(-1.925,0.6) 28(-1.925,0.2) 29(-1.925,-0.2) 30(-1.925,-0.6) 31(-1.925,-1)
  rect 2.8x2.8 smd mask+0.05: 33(0,0)
  Top Layer region: 1.29,-2.255 1.29,-1.595 1.35,-1.595 1.51,-1.755 1.51,-2.255
  Top Layer region: -1.29,-2.255 -1.29,-1.595 -1.35,-1.595 -1.51,-1.755 -1.51,-2.255
  Top Layer region: -2.255,-1.29 -1.595,-1.29 -1.595,-1.35 -1.755,-1.51 -2.255,-1.51
  Top Layer region: -2.255,1.29 -1.595,1.29 -1.595,1.35 -1.755,1.51 -2.255,1.51
  Top Layer region: 2.255,1.29 1.595,1.29 1.595,1.35 1.755,1.51 2.255,1.51
  Top Layer region: 2.255,-1.29 1.595,-1.29 1.595,-1.35 1.755,-1.51 2.255,-1.51
  Top Layer region: 1.29,2.255 1.29,1.595 1.35,1.595 1.51,1.755 1.51,2.255
  Top Layer region: -1.29,2.255 -1.29,1.595 -1.35,1.595 -1.51,1.755 -1.51,2.255
  silkscreen extent -2.25,-2.25 -1.68,-1.68, body extent -2.01,-2.01 2,2.01, height 0.91
ICC_QFN40-EPAD_5X5_P040 [mm]
  rect 0.7x0.2 smd mask+0.05: 1(-2.45,1.8) 2(-2.45,1.4) 3(-2.45,1) 4(-2.45,0.6) 5(-2.45,0.2) 6(-2.45,-0.2) 7(-2.45,-0.6) 8(-2.45,-1) 9(-2.45,-1.4) 10(-2.45,-1.8) 21(2.45,-1.8) 22(2.45,-1.4) 23(2.45,-1) 24(2.45,-0.6) 25(2.45,-0.2) 26(2.45,0.2) 27(2.45,0.6) 28(2.45,1) 29(2.45,1.4) 30(2.45,1.8)
  rect 0.2x0.7 smd mask+0.05: 11(-1.8,-2.45) 12(-1.4,-2.45) 13(-1,-2.45) 14(-0.6,-2.45) 15(-0.2,-2.45) 16(0.2,-2.45) 17(0.6,-2.45) 18(1,-2.45) 19(1.4,-2.45) 20(1.8,-2.45) 31(1.8,2.45) 32(1.4,2.45) 33(1,2.45) 34(0.6,2.45) 35(0.2,2.45) 36(-0.2,2.45) 37(-0.6,2.45) 38(-1,2.45) 39(-1.4,2.45) 40(-1.8,2.45)
  rect 3.8x3.8 smd mask+0.05: 41(0,0)
  silkscreen extent -2.5,-2.5 2.5,2.5, body extent -2.5,-2.5 2.5,2.5, height 0.91
ICC_SC70-6_DCK_R-PDSO-G6_2X1P25_P065 [mm]
  rect 0.4x0.9 smd mask+0.05: 1(-0.65,-1.1) 2(0,-1.1) 3(0.65,-1.1) 4(0.65,1.1) 5(0,1.1) 6(-0.65,1.1)
  silkscreen extent -1.22,-1.38 1.1,0.7, body extent -1.1,-1.05 1.1,1.05, height 1.11
ICC_SOT23-5L_H1P45 [mm]
  rect 0.6x1.3 smd mask+0.05: 1(-0.95,-1.1) 2(0,-1.1) 3(0.95,-1.1) 4(0.95,1.1) 5(-0.95,1.1)
  silkscreen extent -1.75,-1.68 1.6,0.97, body extent -1.52,-1.25 1.52,1.25, height 1.45
ICC_SOT886_XSON6 [mm] "MCD-01514"
  rect 0.3x0.4 smd mask+0.05: 1(-0.5,-0.3) 2(0,-0.3) 3(0.5,-0.3) 4(0.5,0.3) 5(0,0.3) 6(-0.5,0.3)
  silkscreen extent -0.87,-0.65 0.77,0.53, body extent -0.75,-0.53 0.75,0.53, height 0.51
ICC_UFBGA201_176+25_10X10_P065 [mm] "IPC"
  round 0.25 smd mask+0.038: A1(-4.55,4.55) A2(-3.9,4.55) A3(-3.25,4.55) A4(-2.6,4.55) A5(-1.95,4.55) A6(-1.3,4.55) A7(-0.65,4.55) A8(0,4.55) A9(0.65,4.55) A10(1.3,4.55) A11(1.95,4.55) A12(2.6,4.55) A13(3.25,4.55) A14(3.9,4.55) A15(4.55,4.55) B1(-4.55,3.9) B2(-3.9,3.9) B3(-3.25,3.9) B4(-2.6,3.9) B5(-1.95,3.9) B6(-1.3,3.9) B7(-0.65,3.9) B8(0,3.9) B9(0.65,3.9) B10(1.3,3.9) B11(1.95,3.9) B12(2.6,3.9) B13(3.25,3.9) B14(3.9,3.9) B15(4.55,3.9) C1(-4.55,3.25) C2(-3.9,3.25) C3(-3.25,3.25) C4(-2.6,3.25) C5(-1.95,3.25) C6(-1.3,3.25) C7(-0.65,3.25) C8(0,3.25) C9(0.65,3.25) C10(1.3,3.25) C11(1.95,3.25) C12(2.6,3.25) C13(3.25,3.25) C14(3.9,3.25) C15(4.55,3.25) D1(-4.55,2.6) D2(-3.9,2.6) D3(-3.25,2.6) D4(-2.6,2.6) D5(-1.95,2.6) D6(-1.3,2.6) D7(-0.65,2.6) D8(0,2.6) D9(0.65,2.6) D10(1.3,2.6) D11(1.95,2.6) D12(2.6,2.6) D13(3.25,2.6) D14(3.9,2.6) D15(4.55,2.6) E1(-4.55,1.95) E2(-3.9,1.95) E3(-3.25,1.95) E4(-2.6,1.95) E12(2.6,1.95) E13(3.25,1.95) E14(3.9,1.95) E15(4.55,1.95) F1(-4.55,1.3) F2(-3.9,1.3) F3(-3.25,1.3) F4(-2.6,1.3) F6(-1.3,1.3) F7(-0.65,1.3) F8(0,1.3) F9(0.65,1.3) F10(1.3,1.3) F12(2.6,1.3) F13(3.25,1.3) F14(3.9,1.3) F15(4.55,1.3) G1(-4.55,0.65) G2(-3.9,0.65) G3(-3.25,0.65) G4(-2.6,0.65) G6(-1.3,0.65) G7(-0.65,0.65) G8(0,0.65) G9(0.65,0.65) G10(1.3,0.65) G12(2.6,0.65) G13(3.25,0.65) G14(3.9,0.65) G15(4.55,0.65) H1(-4.55,0) H2(-3.9,0) H3(-3.25,0) H4(-2.6,0) H6(-1.3,0) H7(-0.65,0) H8(0,0) H9(0.65,0) H10(1.3,0) H12(2.6,0) H13(3.25,0) H14(3.9,0) H15(4.55,0) J1(-4.55,-0.65) J2(-3.9,-0.65) J3(-3.25,-0.65) J4(-2.6,-0.65) J6(-1.3,-0.65) J7(-0.65,-0.65) J8(0,-0.65) J9(0.65,-0.65) J10(1.3,-0.65) J12(2.6,-0.65) J13(3.25,-0.65) J14(3.9,-0.65) J15(4.55,-0.65) K1(-4.55,-1.3) K2(-3.9,-1.3) K3(-3.25,-1.3) K4(-2.6,-1.3) K6(-1.3,-1.3) K7(-0.65,-1.3) K8(0,-1.3) K9(0.65,-1.3) K10(1.3,-1.3) K12(2.6,-1.3) K13(3.25,-1.3) K14(3.9,-1.3) K15(4.55,-1.3) L1(-4.55,-1.95) L2(-3.9,-1.95) L3(-3.25,-1.95) L4(-2.6,-1.95) L12(2.6,-1.95) L13(3.25,-1.95) L14(3.9,-1.95) L15(4.55,-1.95) M1(-4.55,-2.6) M2(-3.9,-2.6) M3(-3.25,-2.6) M4(-2.6,-2.6) M5(-1.95,-2.6) M6(-1.3,-2.6) M7(-0.65,-2.6) M8(0,-2.6) M9(0.65,-2.6) M10(1.3,-2.6) M11(1.95,-2.6) M12(2.6,-2.6) M13(3.25,-2.6) M14(3.9,-2.6) M15(4.55,-2.6) N1(-4.55,-3.25) N2(-3.9,-3.25) N3(-3.25,-3.25) N4(-2.6,-3.25) N5(-1.95,-3.25) N6(-1.3,-3.25) N7(-0.65,-3.25) N8(0,-3.25) N9(0.65,-3.25) N10(1.3,-3.25) N11(1.95,-3.25) N12(2.6,-3.25) N13(3.25,-3.25) N14(3.9,-3.25) N15(4.55,-3.25) P1(-4.55,-3.9) P2(-3.9,-3.9) P3(-3.25,-3.9) P4(-2.6,-3.9) P5(-1.95,-3.9) P6(-1.3,-3.9) P7(-0.65,-3.9) P8(0,-3.9) P9(0.65,-3.9) P10(1.3,-3.9) P11(1.95,-3.9) P12(2.6,-3.9) P13(3.25,-3.9) P14(3.9,-3.9) P15(4.55,-3.9) R1(-4.55,-4.55) R2(-3.9,-4.55) R3(-3.25,-4.55) R4(-2.6,-4.55) R5(-1.95,-4.55) R6(-1.3,-4.55) R7(-0.65,-4.55) R8(0,-4.55) R9(0.65,-4.55) R10(1.3,-4.55) R11(1.95,-4.55) R12(2.6,-4.55) R13(3.25,-4.55) R14(3.9,-4.55) R15(4.55,-4.55)
  silkscreen extent -5.22,-5.07 5.07,5.23, body extent -5.07,-5.07 5.07,5.07, height 0.61
ICC_VFBGA264_14X14_P080_SOCKET_IRONWOOD_SG-BGA-6112MF [mm] "MCD-03176"
  round 0.36 smd mask+0.05: A1(-6.025,6.4) A2(-5.225,6.4) A3(-4.425,6.4) A4(-3.625,6.4) A5(-2.825,6.4) A6(-2.025,6.4) A7(-1.225,6.4) A8(-0.425,6.4) A9(0.375,6.4) A10(1.175,6.4) A11(1.975,6.4) A12(2.775,6.4) A13(3.575,6.4) A14(4.375,6.4) A15(5.175,6.4) A16(5.975,6.4) A17(6.775,6.4) B1(-6.025,5.6) B2(-5.225,5.6) B3(-4.425,5.6) B4(-3.625,5.6) B5(-2.825,5.6) B6(-2.025,5.6) B7(-1.225,5.6) B8(-0.425,5.6) B9(0.375,5.6) B10(1.175,5.6) B11(1.975,5.6) B12(2.775,5.6) B13(3.575,5.6) B14(4.375,5.6) B15(5.175,5.6) B16(5.975,5.6) B17(6.775,5.6) C1(-6.025,4.8) C2(-5.225,4.8) C3(-4.425,4.8) C4(-3.625,4.8) C5(-2.825,4.8) C6(-2.025,4.8) C7(-1.225,4.8) C8(-0.425,4.8) C9(0.375,4.8) C10(1.175,4.8) C11(1.975,4.8) C12(2.775,4.8) C13(3.575,4.8) C14(4.375,4.8) C15(5.175,4.8) C16(5.975,4.8) C17(6.775,4.8) D1(-6.025,4) D2(-5.225,4) D3(-4.425,4) D4(-3.625,4) D5(-2.825,4) D6(-2.025,4) D7(-1.225,4) D8(-0.425,4) D9(0.375,4) D10(1.175,4) D11(1.975,4) D12(2.775,4) D13(3.575,4) D14(4.375,4) D15(5.175,4) D16(5.975,4) D17(6.775,4) E1(-6.025,3.2) E2(-5.225,3.2) E3(-4.425,3.2) E4(-3.625,3.2) E5(-2.825,3.2) E6(-2.025,3.2) E7(-1.225,3.2) E8(-0.425,3.2) E9(0.375,3.2) E10(1.175,3.2) E11(1.975,3.2) E12(2.775,3.2) E13(3.575,3.2) E14(4.375,3.2) E15(5.175,3.2) E16(5.975,3.2) E17(6.775,3.2) F1(-6.025,2.4) F2(-5.225,2.4) F3(-4.425,2.4) F4(-3.625,2.4) F5(-2.825,2.4) F6(-2.025,2.4) F7(-1.225,2.4) F8(-0.425,2.4) F9(0.375,2.4) F10(1.175,2.4) F11(1.975,2.4) F12(2.775,2.4) F13(3.575,2.4) F14(4.375,2.4) F15(5.175,2.4) F16(5.975,2.4) F17(6.775,2.4) G1(-6.025,1.6) G2(-5.225,1.6) G3(-4.425,1.6) G4(-3.625,1.6) G5(-2.825,1.6) G6(-2.025,1.6) G12(2.775,1.6) G13(3.575,1.6) G14(4.375,1.6) G15(5.175,1.6) G16(5.975,1.6) G17(6.775,1.6) H1(-6.025,0.8) H2(-5.225,0.8) H3(-4.425,0.8) H4(-3.625,0.8) H5(-2.825,0.8) H6(-2.025,0.8) H12(2.775,0.8) H13(3.575,0.8) H14(4.375,0.8) H15(5.175,0.8) H16(5.975,0.8) H17(6.775,0.8) J1(-6.025,0) J2(-5.225,0) J3(-4.425,0) J4(-3.625,0) J5(-2.825,0) J6(-2.025,0) J12(2.775,0) J13(3.575,0) J14(4.375,0) J15(5.175,0) J16(5.975,0) J17(6.775,0) K1(-6.025,-0.8) K2(-5.225,-0.8) K3(-4.425,-0.8) K4(-3.625,-0.8) K5(-2.825,-0.8) K6(-2.025,-0.8) K12(2.775,-0.8) K13(3.575,-0.8) K14(4.375,-0.8) K15(5.175,-0.8) K16(5.975,-0.8) K17(6.775,-0.8) L1(-6.025,-1.6) L2(-5.225,-1.6) L3(-4.425,-1.6) L4(-3.625,-1.6) L5(-2.825,-1.6) L6(-2.025,-1.6) L12(2.775,-1.6) L13(3.575,-1.6) L14(4.375,-1.6) L15(5.175,-1.6) L16(5.975,-1.6) L17(6.775,-1.6) M1(-6.025,-2.4) M2(-5.225,-2.4) M3(-4.425,-2.4) M4(-3.625,-2.4) M5(-2.825,-2.4) M6(-2.025,-2.4) M7(-1.225,-2.4) M8(-0.425,-2.4) M9(0.375,-2.4) M10(1.175,-2.4) M11(1.975,-2.4) M12(2.775,-2.4) M13(3.575,-2.4) M14(4.375,-2.4) M15(5.175,-2.4) M16(5.975,-2.4) M17(6.775,-2.4) N1(-6.025,-3.2) N2(-5.225,-3.2) N3(-4.425,-3.2) N4(-3.625,-3.2) N5(-2.825,-3.2) N6(-2.025,-3.2) N7(-1.225,-3.2) N8(-0.425,-3.2) N9(0.375,-3.2) N10(1.175,-3.2) N11(1.975,-3.2) N12(2.775,-3.2) N13(3.575,-3.2) N14(4.375,-3.2) N15(5.175,-3.2) N16(5.975,-3.2) N17(6.775,-3.2) P1(-6.025,-4) P2(-5.225,-4) P3(-4.425,-4) P4(-3.625,-4) P5(-2.825,-4) P6(-2.025,-4) P7(-1.225,-4) P8(-0.425,-4) P9(0.375,-4) P10(1.175,-4) P11(1.975,-4) P12(2.775,-4) P13(3.575,-4) P14(4.375,-4) P15(5.175,-4) P16(5.975,-4) P17(6.775,-4) R1(-6.025,-4.8) R2(-5.225,-4.8) R3(-4.425,-4.8) R4(-3.625,-4.8) R5(-2.825,-4.8) R6(-2.025,-4.8) R7(-1.225,-4.8) R8(-0.425,-4.8) R9(0.375,-4.8) R10(1.175,-4.8) R11(1.975,-4.8) R12(2.775,-4.8) R13(3.575,-4.8) R14(4.375,-4.8) R15(5.175,-4.8) R16(5.975,-4.8) R17(6.775,-4.8) T1(-6.025,-5.6) T2(-5.225,-5.6) T3(-4.425,-5.6) T4(-3.625,-5.6) T5(-2.825,-5.6) T6(-2.025,-5.6) T7(-1.225,-5.6) T8(-0.425,-5.6) T9(0.375,-5.6) T10(1.175,-5.6) T11(1.975,-5.6) T12(2.775,-5.6) T13(3.575,-5.6) T14(4.375,-5.6) T15(5.175,-5.6) T16(5.975,-5.6) T17(6.775,-5.6) U1(-6.025,-6.4) U2(-5.225,-6.4) U3(-4.425,-6.4) U4(-3.625,-6.4) U5(-2.825,-6.4) U6(-2.025,-6.4) U7(-1.225,-6.4) U8(-0.425,-6.4) U9(0.375,-6.4) U10(1.175,-6.4) U11(1.975,-6.4) U12(2.775,-6.4) U13(3.575,-6.4) U14(4.375,-6.4) U15(5.175,-6.4) U16(5.975,-6.4) u17(6.775,-6.4)
  round 0 hole 1.61 unplated mask+0.05: NPTH1(-8.363,8.363) NPTH2(8.363,8.363) NPTH3(8.363,-8.363) NPTH4(-8.363,-8.363)
  round 0 hole 0.85 unplated mask+0.05: NPTH5(-8.363,-3.283) NPTH6(8.363,5.823)
  Bottom Layer keep-out circle w0.01: c-8.362,8.362 r2.5
  Bottom Layer keep-out circle w0.01: c8.363,-8.363 r2.5
  Bottom Layer keep-out circle w0.01: c-8.363,-8.363 r2.5
  Bottom Layer keep-out lines w0.01: 7.492,6.019 cw(c8.363,8.363) 9.254,6.027
  Keep-Out Layer circle w0.01: c8.363,5.823 r0.7
  Keep-Out Layer circle w0.01: c-8.363,-3.283 r0.7
  Keep-Out Layer circle w0.01: c-8.362,8.362 r1.1
  Keep-Out Layer circle w0.01: c8.363,8.363 r1.1
  Keep-Out Layer circle w0.01: c8.362,-8.362 r1.1
  Keep-Out Layer circle w0.01: c-8.363,-8.363 r1.1
  silkscreen extent -9.61,-9.61 9.61,9.61, body extent -10.38,-10.36 10.36,10.38, height 9.86
ICC_VFDFPN8-EPAD_3X3_P065 [mm] "MCD-02243"
  rect 0.35x0.55 smd mask+0.05: 1(-0.975,-1.475) 2(-0.325,-1.475) 3(0.325,-1.475) 4(0.975,-1.475) 5(0.975,1.475) 6(0.325,1.475) 7(-0.325,1.475) 8(-0.975,1.475)
  rect 2.55x1.65 smd mask+0.05: 9(0,0)
  Top Layer region: -1.15,1.2 -1.137,1.133 -1.099,1.076 -1.042,1.038 -0.975,1.025 -0.975,1.025 -0.908,1.038 -0.851,1.076 -0.813,1.133 -0.8,1.2 -0.8,1.2
  Top Layer region: -0.5,1.2 -0.487,1.133 -0.449,1.076 -0.392,1.038 -0.325,1.025 -0.325,1.025 -0.258,1.038 -0.201,1.076 -0.163,1.133 -0.15,1.2 -0.15,1.2
  Top Layer region: 0.15,1.2 0.163,1.133 0.201,1.076 0.258,1.038 0.325,1.025 0.325,1.025 0.392,1.038 0.449,1.076 0.487,1.133 0.5,1.2 0.5,1.2
  Top Layer region: 0.8,1.2 0.813,1.133 0.851,1.076 0.908,1.038 0.975,1.025 0.975,1.025 1.042,1.038 1.099,1.076 1.137,1.133 1.15,1.2 1.15,1.2
  Top Layer region: 1.15,-1.2 1.137,-1.133 1.099,-1.076 1.042,-1.038 0.975,-1.025 0.975,-1.025 0.908,-1.038 0.851,-1.076 0.813,-1.133 0.8,-1.2 0.8,-1.2
  Top Layer region: 0.5,-1.2 0.487,-1.133 0.449,-1.076 0.392,-1.038 0.325,-1.025 0.325,-1.025 0.258,-1.038 0.201,-1.076 0.163,-1.133 0.15,-1.2 0.15,-1.2
  Top Layer region: -0.15,-1.2 -0.163,-1.133 -0.201,-1.076 -0.258,-1.038 -0.325,-1.025 -0.325,-1.025 -0.392,-1.038 -0.449,-1.076 -0.487,-1.133 -0.5,-1.2 -0.5,-1.2
  Top Layer region: -0.8,-1.2 -0.813,-1.133 -0.851,-1.076 -0.908,-1.038 -0.975,-1.025 -0.975,-1.025 -1.042,-1.038 -1.099,-1.076 -1.137,-1.133 -1.15,-1.2 -1.15,-1.2
  silkscreen extent -1.5,-1.5 1.5,1.5, body extent -1.5,-1.5 1.5,1.5, height 1
ICC_WSON8-EPAD_2X2_P050 [mm] "MCD-02194"
  rect 0.5x0.3 smd paste+0 mask+0.05: 1(-0.9,0.75) 2(-0.9,0.25) 3(-0.9,-0.25) 4(-0.9,-0.75) 5(0.9,-0.75) 6(0.9,-0.25) 7(0.9,0.25) 8(0.9,0.75)
  rect 0.9x1.6 smd paste+0 mask+0.05: 9(0,0)
  silkscreen extent -0.5,-1 0.5,1, body extent -1,-1 1,1, height 0.81
IND_0603_LSMCA_H1P0 [mm]
  rect 1x1 smd mask+0.05: 1(-1,0) 2(1,0)
  silkscreen extent -0.3,-0.5 0.3,0.5, body extent -0.9,-0.5 0.9,0.5, height 1
IND_4025_WURTH_74404043022A [mm] "MCD-02242"
  rect 1.5x4.4 smd mask+0.05: 1(-1.525,0) 2(1.525,0)
  silkscreen extent -0.63,-2.1 0.63,2.1, body extent -2.1,-2.1 2.1,2.1, height 2.5
IND_MURATA_DFE201612P [mm] "MCD-01491"
  rect 0.8x1.8 smd mask+0.05: 1(-0.8,0) 2(0.8,0)
  silkscreen extent -0.28,-0.9 0.28,0.9, body extent -1.1,-0.9 1.1,0.9, height 1.2
L0603 [mm]
  rect 0.8x0.95 smd mask+0.05: 1(-0.8,0) 2(0.8,0)
  silkscreen extent -1.33,-0.6 1.33,0.6, body extent -0.87,-0.47 0.87,0.47, height 0.95
L1210_LQH [mm]
  rect 1.7x3.1 smd mask+0.05: 1(-1.1,0) 2(1.1,0)
  silkscreen extent -2.05,-1.65 2.05,1.65, body extent -1.75,-1.35 1.75,1.35, height 2
LED_0603_OSRAM_LG-Q396-PS-35_GREEN_1A2K_H0P4 [mm]
  rect 0.8x0.8 smd mask+0.05: 1(-0.75,0) 2(0.75,0)
  silkscreen extent -0.85,-0.53 1.28,0.53, body extent -0.85,-0.45 0.85,0.45, height 0.6
LED_0603_VISHAY_VLMS1300-GS08_RED_1A2K_H0P8 [mm]
  rect 0.8x0.8 smd mask+0.05: 1(-0.75,0) 2(0.75,0)
  silkscreen extent -0.85,-0.53 1.28,0.53, body extent -0.85,-0.45 0.85,0.45, height 0.8
LED_BI-GR_WE-150141SV73110 [mm] "MCD-02631"
  rect 1.1x1.5 smd mask+0.05: 1(-0.75,1.5) 2(0.75,1.5) 3(-0.75,-1.5) 4(0.75,-1.5)
  silkscreen extent -1.65,-1.85 1.5,1.7, body extent -1.5,-1.85 1.5,1.85, height 2.1
LINK200 [mm]
  rect 0.2x0.35 smd paste-10 mask+0.05: 1(0,-0.225) 2(0,0.225)
MIC_STM_MP23DB01MMTR [mm]
  rect 0.725x0.522 smd mask+0.05: 1(-0.838,1.364) 2(-0.838,0.542) 4(0.838,0.542) 5(0.838,1.364)
  round 0.2 smd mask+0.05: 3(0,-1.373)
  round 0 hole 0.5 unplated mask+0.05: 6(0,-0.71)
  Top Layer circle w0.3: c0,-0.71 r0.663
  silkscreen extent -1.33,-1.75 1.33,1.75, body extent -1.33,-1.76 1.33,1.75, height 1.09
MOS_SC89-3L [mm] "MCD-02221"
  rect 0.46x0.65 smd mask+0.05: 1(-0.5,-0.55) 2(0.5,-0.55) 3(0,0.55)
  silkscreen extent -0.85,-0.48 0.85,0.48, body extent -0.85,-0.85 0.85,0.85, height 0.85
MOS_SOT23 [mm]
  rect 1x1.4 smd mask+0.05: 1(-0.95,-1.1) 2(0.95,-1.1) 3(0,1.1)
  silkscreen extent -1.63,-0.82 1.63,0.82, body extent -1.56,-1.25 1.56,1.25, height 1.1
MOS_SOT23-5L [mm]
  rect 0.6x1.3 smd mask+0.05: 1(-0.95,-1.1) 2(0,-1.1) 3(0.95,-1.1) 4(0.95,1.1) 5(-0.95,1.1)
  silkscreen extent -1.6,-0.95 1.6,0.97, body extent -1.52,-1.25 1.52,1.25, height 1.45
NPN_SOT23 [mm]
  rect 1x1.4 smd mask+0.05: 1(-0.95,-1.1) 2(0.95,-1.1) 3(0,1.1)
  silkscreen extent -1.63,-0.82 1.63,0.82, body extent -1.56,-1.25 1.56,1.25, height 1.1
PowerFLAT_5x6 [mm] "MCD-02152"
  rect 0.65x1.25 smd mask+0.05: 1(1.905,2.675) 2(0.635,2.675) 3(-0.635,2.675) 4(-1.905,2.675) 5(-1.905,-2.675) 6(-0.635,-2.675) 7(0.635,-2.675) 8(1.905,-2.675)
  Top Layer region: 0.2,-3.3 0.95,-3.3 0.95,-2.75 1.575,-2.75 1.575,-3.3 2.3,-3.3 2.3,-2.3 2.7,-2.3 2.7,-1.5 2.3,-1.5 2.3,0.15 2.7,0.15 2.7,0.975 2.3,0.975 2.3,1.15 0.2,1.15
  Top Layer region: -0.2,-3.3 -0.95,-3.3 -0.95,-2.75 -1.575,-2.75 -1.575,-3.3 -2.3,-3.3 -2.3,-2.3 -2.7,-2.3 -2.7,-1.5 -2.3,-1.5 -2.3,0.15 -2.7,0.15 -2.7,0.975 -2.3,0.975 -2.3,1.15 -0.2,1.15
  silkscreen extent -2.5,-3 2.5,3, body extent -2.6,-3.08 2.6,3.07, height 1
PTH_350_700 [mm]
  round 7 hole 3.5 mask+0.05: 1(0,0)
  silkscreen extent -3.75,-3.75 3.75,3.75
PTH_450_900 [mm] "MCD-01612"
  round 9 hole 4.5 mask+0.05: 1(0,0)
  silkscreen extent -4.75,-4.75 4.75,4.75
R0402 [mm]
  rect 0.51x0.7 smd mask+0.05: 1(-0.45,0) 2(0.45,0)
  body extent -0.52,-0.3 0.52,0.3, height 0.4
R0603 [mm]
  rect 0.64x1 smd mask+0.05: 1(-0.7,0) 2(0.7,0)
  silkscreen extent -1.05,-0.58 1.05,0.58, body extent -0.9,-0.5 0.9,0.5, height 0.56
R0805 [mm]
  rect 0.85x1.3 smd mask+0.05: 1(-0.875,0) 2(0.875,0)
  silkscreen extent -0.33,-0.67 0.33,0.67, body extent -1.05,-0.68 1.05,0.68, height 0.65
REG_SOT223-TAB [mm]
  rect 1.5x1.65 smd mask+0.05: 1(-2.3,-3.175) 2(0,-3.175) 3(2.3,-3.175)
  rect 3.5x1.65 smd mask+0.05: 4(0,3.175)
  silkscreen extent -3.35,-2.15 3.35,2.12, body extent -3.35,-3.48 3.35,3.48, height 1.8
